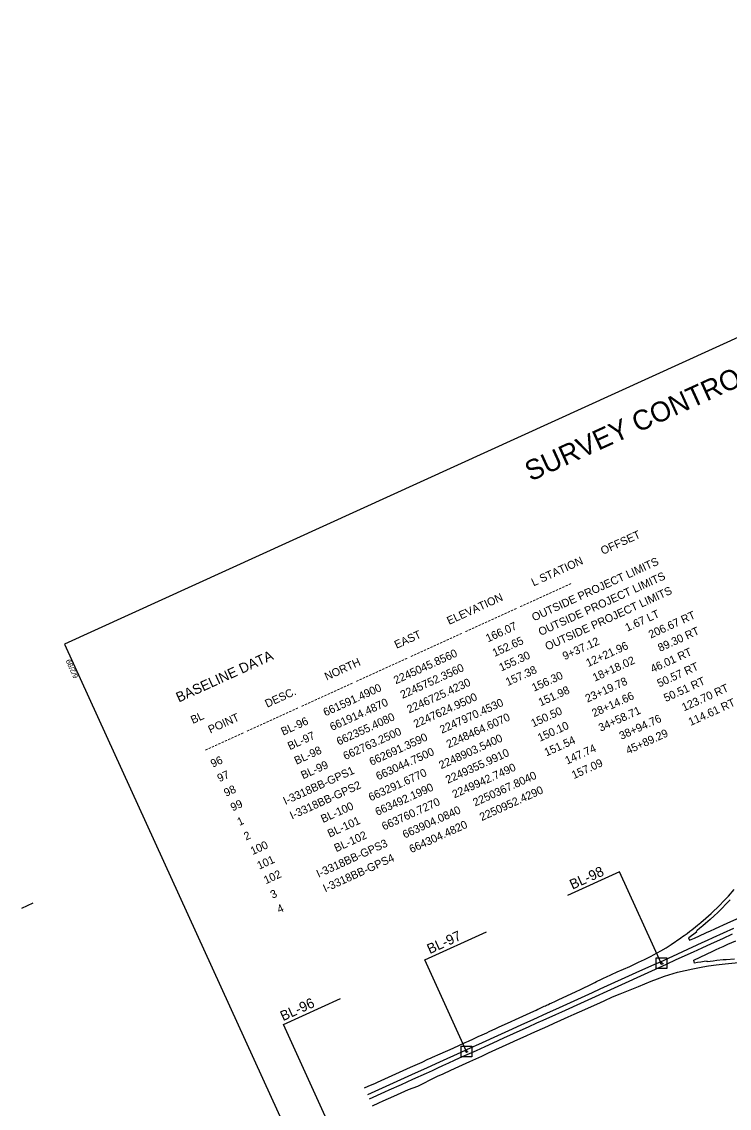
# Model space of a CAD drawing. Extents: x 2243531 to 2252747, y 658714 to 667210.
# Drawn here: x 2243531 to 2247065, y 661631 to 667061 of the extents above; entities that cross this region are included whole.
import ezdxf

# ---------------------------------------------------------------- set-up
doc = ezdxf.new("R2010")
doc.units = 0
for name, color, linetype in [('CTL NGS Horizontal CELL', 7, 'Continuous'), ('CTL Sheet Border CELL', 7, 'Continuous'), ('CTL Sheet Text', 7, 'Continuous'), ('CTL Supplemental Horizontal and Vertical CELL', 7, 'Continuous'), ('CTL Supplemental Horizontal and Vertical Cogo Comment', 7, 'Continuous'), ('CTL Supplemental Horizontal and Vertical Cogo Elevation', 7, 'Continuous'), ('CTL Supplemental Horizontal and Vertical Cogo Number', 7, 'Continuous'), ('CTL Supplemental Horizontal and Vertical Text', 7, 'Continuous'), ('Exist Roads EOP', 7, 'Continuous')]:
    doc.layers.add(name, color=color, linetype=linetype)

msp = doc.modelspace()

# ---------------------------------------------------------------- linework, layer by layer
at = {"layer": 'CTL NGS Horizontal CELL'}
for p, q in [((2246516.9, 662813), (2246256.4, 662694.3)), ((2246725.4, 662355.4), (2246516.9, 662813)), ((2245543.8, 662372.1), (2245852, 662512.5)), ((2245752.4, 661914.5), (2245543.8, 662372.1)), ((2244837.3, 662049.1), (2245122, 662178.8)), ((2245045.9, 661591.5), (2244837.3, 662049.1))]:
    msp.add_line(p, q, dxfattribs=at)
at = {"layer": 'CTL Sheet Border CELL'}
msp.add_line((2243530.5, 662630.9), (2243587.4, 662656.8), dxfattribs=at)
msp.add_lwpolyline([(2250569.7, 667061), (2243744.8, 663951.1), (2245921.8, 659173.7), (2252746.6, 662283.7)], close=True, dxfattribs=at)
at = {"layer": 'CTL Supplemental Horizontal and Vertical CELL'}
for p, q in [((2246725.4, 662355.4), (2246725.4, 662355.4)), ((2246725.4, 662355.4), (2246725.4, 662355.4)), ((2246725.4, 662355.4), (2246725.4, 662355.4)), ((2245752.4, 661914.5), (2245752.4, 661914.5)), ((2245752.4, 661914.5), (2245752.4, 661914.5)), ((2245752.4, 661914.5), (2245752.4, 661914.5))]:
    msp.add_line(p, q, dxfattribs=at)
for points in [[(2246699, 662382), (2246752.3, 662382), (2246752.3, 662328.6), (2246699, 662328.6)], [(2246720.2, 662355.4), (2246725.4, 662360.7), (2246730.7, 662355.4), (2246725.5, 662350.2)], [(2246720.2, 662355.4), (2246725.4, 662360.7), (2246730.7, 662355.4), (2246725.5, 662350.2)], [(2245725.9, 661941.1), (2245779.3, 661941.1), (2245779.3, 661887.7), (2245725.9, 661887.7)], [(2245747.1, 661914.5), (2245752.4, 661919.7), (2245757.6, 661914.5), (2245752.4, 661909.3)], [(2245747.1, 661914.5), (2245752.4, 661919.7), (2245757.6, 661914.5), (2245752.4, 661909.3)]]:
    msp.add_lwpolyline(points, close=True, dxfattribs=at)
at = {"layer": 'Exist Roads EOP'}
for points in [[(2245242.4, 661733), (2245260.5, 661741.1), (2245297.6, 661757), (2245308.1, 661761.9), (2245326.7, 661770.2), (2245473, 661835.7), (2245530.1, 661861.9), (2245559, 661875.6), (2245571.9, 661881.4), (2245582.4, 661885.9), (2245621.2, 661903.4), (2245685.2, 661931.9), (2245745.3, 661958.9), (2245761.6, 661966.8), (2245786.6, 661978.7), (2245810.1, 661989.1), (2245830.4, 661998.2), (2245842.9, 662003.7), (2245853.1, 662008.6), (2245865, 662014), (2245899.1, 662029.8), (2245916.1, 662037.1), (2245957, 662056.2), (2246015.4, 662082.7), (2246070.2, 662108), (2246088.3, 662116.5), (2246100.6, 662121.9), (2246107.8, 662125.4), (2246113, 662127.9), (2246120.2, 662131.2), (2246130.8, 662136.2), (2246140.2, 662140.5), (2246146.9, 662143.5), (2246152.5, 662145.9), (2246161.2, 662150.2), (2246167.9, 662153.7), (2246174.9, 662156.9), (2246196.1, 662166.4), (2246210.6, 662173), (2246235.7, 662184.6), (2246296.8, 662212.3), (2246324.7, 662225.9), (2246375.9, 662250.9), (2246392.6, 662259.4), (2246401.5, 662263.8), (2246411.8, 662269.1), (2246416.6, 662271.1), (2246439.7, 662282.2), (2246448.7, 662286.3), (2246476.2, 662298.7), (2246505.5, 662312.4), (2246567.7, 662339.8), (2246611.6, 662360.8), (2246642.2, 662374.7), (2246665.4, 662386.5), (2246674.8, 662391.6), (2246686.7, 662397.8), (2246722.5, 662417.8), (2246748.9, 662433.5), (2246774.5, 662449.6), (2246823.1, 662483.1), (2246831.8, 662489.1), (2246840.3, 662494.3), (2246854.7, 662504.3), (2246868.1, 662515.4), (2246877.7, 662522.5), (2246896.2, 662537.3), (2246906.2, 662545.6), (2246915, 662552.6), (2246923, 662559), (2246948.2, 662580.7), (2246974.9, 662604.8), (2246986.3, 662615.1), (2247005.6, 662633.9), (2247048.3, 662678.1), (2247060.5, 662690.8), (2247089.2, 662724)], [(2247069, 662673.1), (2247007.3, 662609.4), (2246989.7, 662593.2), (2246969.8, 662575.1), (2246958.2, 662564.5), (2246945.8, 662553.5), (2246933.4, 662543), (2246924.8, 662535.9), (2246915.8, 662528.6), (2246903.8, 662519.2), (2246898.9, 662514.8), (2246900.4, 662511.3), (2246862.9, 662482.7), (2246860.4, 662482), (2246866.4, 662470.3), (2246891.9, 662481.8), (2246944, 662505.6), (2246955.1, 662510.5), (2246967.1, 662516.3), (2246995.6, 662529), (2247054.6, 662555.6), (2247231.9, 662636.4)], [(2247086, 662529.3), (2246982.9, 662482.5), (2246954.2, 662469.4), (2246927.7, 662457.2), (2246733.9, 662368.4), (2246676.3, 662343), (2246598.3, 662307.5), (2246418, 662225.6), (2246379.6, 662207.9), (2246196.3, 662124.7), (2246154.9, 662105.9), (2246084.2, 662073.4), (2246027.5, 662047.8), (2245980.1, 662026.3), (2245925.6, 662001.2), (2245811.7, 661949.8), (2245773.4, 661932.2), (2245723.4, 661909.3), (2245616.8, 661861.1), (2245555.4, 661833.4), (2245477.7, 661797.9), (2245385.9, 661756), (2245258.3, 661698.3)], [(2245267.7, 661677.5), (2245345.1, 661712.3), (2245366, 661722.3), (2245426.8, 661749.7), (2245483.9, 661775.7), (2245553, 661807.1), (2245581.9, 661820.2), (2245602.8, 661830.1), (2245611.8, 661834.3), (2245631, 661842.8), (2245651.9, 661852.4), (2245661, 661856.6), (2245696.2, 661872.2), (2245732.2, 661888.9), (2245801.5, 661920.1), (2245844.7, 661939.9), (2245884.8, 661958.1), (2245938.2, 661982.4), (2245987.3, 662004.4), (2246005.7, 662012.7), (2246061.2, 662038.4), (2246104.3, 662058.1), (2246134.9, 662071.8), (2246199.2, 662100.3), (2246228, 662113.1), (2246341.8, 662165.3), (2246509.6, 662241.9), (2246659.1, 662309.7), (2246750.5, 662351.3), (2246800, 662373.8), (2246886.1, 662413.3), (2246928.7, 662432.5), (2246976.5, 662453.8), (2247032.5, 662479.4), (2247081.5, 662502)], [(2247091.7, 662376.8), (2247049.4, 662373.4), (2247033.7, 662372.1), (2247003.3, 662369), (2246985, 662366.6), (2246969.1, 662364.7), (2246954.7, 662362.8), (2246954, 662366.7), (2246939.6, 662364), (2246922.4, 662361.6), (2246906.6, 662359.1), (2246891.5, 662356.1), (2246888, 662371.7), (2246950.9, 662401.8), (2246983.2, 662416.3), (2246995.6, 662422.1), (2247017.6, 662432), (2247034.2, 662439.5), (2247057.7, 662450.3), (2247097.6, 662468.1)], [(2245283.2, 661643.6), (2245314.5, 661658.2), (2245336.4, 661667.6), (2245389.1, 661692), (2245425.2, 661708.2), (2245461.7, 661724.6), (2245509.9, 661741), (2245539.2, 661756.7), (2245570.3, 661773.4), (2245606.9, 661790.6), (2245635.7, 661803.7), (2245674.7, 661821.8), (2245714.7, 661840), (2245768.8, 661865.1), (2245828, 661891.8), (2245861.6, 661907.3), (2245898.4, 661923.8), (2245932.6, 661939.3), (2245968.7, 661955.9), (2246009, 661974), (2246051, 661993.6), (2246078.3, 662005.6), (2246105.8, 662017.6), (2246158.4, 662041.8), (2246190.3, 662055.9), (2246223.4, 662070.9), (2246260.8, 662087.5), (2246290.5, 662101.5), (2246343.9, 662124.3), (2246376.6, 662139.7), (2246403.9, 662151.9), (2246439.4, 662168.2), (2246482.3, 662187.2), (2246519.6, 662202.3), (2246544.1, 662212.5), (2246610.6, 662240.2), (2246675.2, 662266.5), (2246706.7, 662278.4), (2246741.9, 662290.8), (2246784.4, 662303.7), (2246806, 662310.4), (2246883.3, 662327.6), (2246932.5, 662338.3), (2246961.7, 662342.9), (2246999.4, 662347.9), (2247044.5, 662353.5), (2247111.5, 662359.2)]]:
    msp.add_lwpolyline(points, dxfattribs=at)

# ---------------------------------------------------------------- texts
at = {"layer": 'CTL Sheet Border CELL'}
for s, height, rotation, p in [('SURVEY CONTROL SHEET I-3318-BB', 100, 24.4979, (2246072.9, 664762.6)), ('BASELINE DATA', 50.001, 24.4979, (2244315.3, 663658.4)), ('6/2/99', 26.25, 114.4979, (2243814.6, 663786.5))]:
    msp.add_text(s, height=height, rotation=rotation, dxfattribs=at).set_placement(p)
at = {"layer": 'CTL Sheet Text'}
for s, p in [('    POINT          DESC.           NORTH             EAST          ELEVATION           L STATION       OFFSET', (2244418.5, 663478.3)), ('96                      BL-96      661591.4900     2245045.8560           166.07      OUTSIDE PROJECT LIMITS                 ', (2244484.8, 663332.7)), ('97                      BL-97      661914.4870     2245752.3560           152.65      OUTSIDE PROJECT LIMITS                 ', (2244518, 663259.9)), ('------------ ---------------- ---------------- ---------------- ---------------- ---------------- ----------------', (2244451.6, 663405.5)), ('98                      BL-98      662355.4080     2246725.4230           155.30      OUTSIDE PROJECT LIMITS                 ', (2244551.2, 663187.1)), ('99                      BL-99      662763.2500     2247624.9500           157.38          9+37.12          1.67 LT', (2244584.3, 663114.3)), ('1               I-3318BB-GPS1      662691.3590     2247970.4530           156.30         12+21.96        206.67 RT', (2244617.5, 663041.5)), ('2               I-3318BB-GPS2      663044.7500     2248464.6070           151.98         18+18.02         89.30 RT', (2244650.7, 662968.7)), ('100                    BL-100      663291.6770     2248903.5400           150.50         23+19.78         46.01 RT', (2244683.9, 662895.9)), ('101                    BL-101      663492.1990     2249355.9910           150.10         28+14.66         50.57 RT', (2244717, 662823.1)), ('102                    BL-102      663760.7270     2249942.7490           151.54         34+58.71         50.51 RT', (2244750.2, 662750.3)), ('3               I-3318BB-GPS3      663904.0840     2250367.8040           147.74         38+94.76        123.70 RT', (2244783.4, 662677.5)), ('4               I-3318BB-GPS4      664304.4820     2250952.4290           157.09         45+89.29        114.61 RT', (2244816.6, 662604.7)), ('BL', (2244385.3, 663551.1))]:
    msp.add_text(s, height=40, rotation=24.4979, dxfattribs=at).set_placement(p)
at = {"layer": 'CTL Supplemental Horizontal and Vertical Cogo Comment'}
for s, p in [('BL-98', (2246727.9, 662350.4)), ('BL-98', (2246727.9, 662350.4)), ('BL-97', (2245754.9, 661909.5)), ('BL-97', (2245754.9, 661909.5))]:
    msp.add_text(s, height=2.5, dxfattribs=at).set_placement(p)
at = {"layer": 'CTL Supplemental Horizontal and Vertical Cogo Elevation'}
for s, p in [('155.30', (2246727.9, 662354.2)), ('155.30', (2246727.9, 662354.2)), ('152.65', (2245754.9, 661913.2)), ('152.65', (2245754.9, 661913.2))]:
    msp.add_text(s, height=2.5, dxfattribs=at).set_placement(p)
at = {"layer": 'CTL Supplemental Horizontal and Vertical Cogo Number'}
for s, p in [('98', (2246727.9, 662357.9)), ('98', (2246727.9, 662357.9)), ('97', (2245754.9, 661917)), ('97', (2245754.9, 661917))]:
    msp.add_text(s, height=2.5, dxfattribs=at).set_placement(p)
at = {"layer": 'CTL Supplemental Horizontal and Vertical Text'}
for s, p in [('BL-98', (2246281.4, 662723)), ('BL-97', (2245568.9, 662400.8)), ('BL-96', (2244835.8, 662065.7))]:
    msp.add_text(s, height=50, rotation=24.4979, dxfattribs=at).set_placement(p)

doc.saveas('drawing.dxf')
